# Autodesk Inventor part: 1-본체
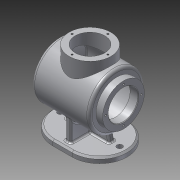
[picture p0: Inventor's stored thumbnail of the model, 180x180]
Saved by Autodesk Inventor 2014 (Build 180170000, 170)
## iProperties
Created: 2016-04
Part Number: 1-본체
Material: 알루미늄 6061
Document SubType Name: Modeling
Designer: owner
Density: 2.71 g/cm^3
Appearance: 알루미늄 - 평지
Mass: 916.245 g
Surface Area: 1253.5 cm^2
Volume: 338.098 cm^3
Author: owner
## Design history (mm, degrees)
sketch "스케치1"
  geometry: L1 (-67.5, 50)-(67.5, 50); L2 (67.5, 50)-(67.5, -50); L3 (67.5, -50)-(-67.5, -50); L4 (-67.5, -50)-(-67.5, 50); 3 further points
  constraints: 8 end point, 2 midpoint, 2 parallel, 1 horizontal, 1 horizontal alignment, 1 perpendicular, 1 vertical alignment
  dimensions: "d0" = 135 distance of L1.start L1.end; "d1" = 100 distance of L1.end L2.end
extrude "돌출1" new body sketch "스케치1" distance "d2" = 10; taper "d3" = 0 deg
fillet "모깎기1" dims "d4" = 50
node "작업 평면1"
sketch "스케치6"
  geometry: L1 (-67.5, 0)-(-67.5, 10) reference; L2 (67.5, 0)-(67.5, 10) reference; L3 (17.5, 10)-(67.5, 10) reference; L4 (-17.5, 10)-(17.5, 10) reference; L5 (-67.5, 10)-(-17.5, 10) reference; L6 (-61, 79)-(61, 79); L7 (67.5, 0)-(17.5, 0) reference; L8 (54.623, 129)-(-49, 129); L9 (-49, 129)-(-49, 117); L10 (-49, 117)-(-61, 117); L11 (-61, 117)-(-61, 106); L12 (52.287, 126)-(-46, 126); L13 (-46, 126)-(-46, 106); L14 (-46, 106)-(-61, 106); A1 r 199.192 centre (-138.192, 79) between (61, 79) and (54.623, 129); A2 r 196.192 centre (-138.192, 79) between (58, 79) and (52.287, 126); 2 further points
  constraints: 16 end point, 5 perpendicular, 4 point on circle, 3 parallel, 2 centre point, 2 point on line, 2 vertical alignment, 1 midpoint
  dimensions: "d53" = 79 distance between parallel lines of L6 L7; "d54" = 122 distance of L6.start L6.end; "d56" = 100 diameter of L8 L6; "d57" = 12 distance of L9.end L10.end; "d58" = 76 diameter of L10 L6; "d61" = 54 diameter of L14 L6; "d62" = 15 distance of L11.end L13.end; "d63" = 3 distance between parallel lines of L8 L12; "d64" = 3 radial gap between concentric circles of A2 A1 (= d63); "d65" = 199.19182 radius of A1
revolve "회전3" sketch "스케치6" stored, may be unused: angle "d66" = 90 deg
node "작업 평면2"
sketch "스케치7"
  geometry: C1 r 38 at (0, 0); 1 further point
  constraints: 1 centre point, 1 coincident
  dimensions: "d68" = 76 diameter of C1
extrude "돌출3" join sketch "스케치7" stored distance "d69" = 12; taper "d70" = 0 deg
node "작업 평면4"
sketch "스케치10"
  geometry: L1 (-50, 10)-(50, 10) reference; L2 (-40, 49)-(-40, 10); L3 (40, 49)-(40, 10); L4 (-40, 10)-(40, 10); A1 r 50 centre (0, 79) between (-40, 49) and (40, 49) reference; A2 r 50 centre (0, 79) between (-40, 49) and (40, 49); 1 further point
  constraints: 6 end point, 4 point on circle, 2 point on line, 1 centre point, 1 coincident, 1 collinear, 1 parallel, 1 perpendicular
  dimensions: "d73" = 40 distance from line of point (0, 0) L3; "d74" = 40 horizontal distance of L2.end point (0, 0) (= d73)
extrude "돌출4" join sketch "스케치10" stored distance "d75" = 10; taper "d76" = 0 deg
sketch "스케치11"
  geometry: C1 r 38 at (0, 0) reference; C2 r 27 at (0, 0) reference; C3 r 32.5 at (0, 0); 2 further points
  constraints: 1 centre point, 1 coincident, 1 horizontal alignment
  dimensions: "d77" = 65 diameter of C3; "d78" = 32.5 distance of C1.centre point (-32.5, 0)
hole "구멍2" sketch "스케치11" at (-32.5, 0) diameter "d79" = 3.242; stored, may be unused: countersink angle "d83" = 90 deg, drill point angle "d85" = 118 deg; dims "d80" = 8, "d81" = 4, "d82" = 2, "d84" = 10
node "작업 평면5"
sketch "스케치12"
  geometry: L1 (-49, 29)-(54.623, 29) reference; L2 (-67.5, 10)-(-17.5, 10) reference; L3 (-5, 49)-(-5, 10) reference; L4 (17.5, 10)-(-17.5, 10) reference; L5 (-40, 10)-(-36.65, 29); 1 further point
  constraints: 2 end point, 2 point on line
  dimensions: "d90" = 40 horizontal distance of point (0, 0) L5.start; "d91" = 100 deg angle of L5 L2
feature "리브1" sketch "스케치12" dims "d92" = 1, "d93" = 10, "d94" = 0, "d95" = 0, "d96" = 1, "d97" = 1
sketch "스케치13" dims "d98" = 65
  geometry: C1 r 38 at (0, 0) reference; 2 further points
  constraints: 2 horizontal alignment, 1 coincident, 2 other
hole "구멍3" sketch "스케치13" at (32.5, 0) diameter "d99" = 3.242; stored, may be unused: countersink angle "d103" = 90 deg, drill point angle "d105" = 118 deg; dims "d100" = 8, "d101" = 4, "d102" = 2, "d104" = 10
sketch "스케치14"
  geometry: C1 r 5 at (-54, 0); A1 r 50 centre (-17.5, 0) between (-17.5, 50) and (-17.5, -50) reference; 1 further point
  constraints: 1 centre point, 1 horizontal alignment
  dimensions: "d109" = 10 diameter of C1; "d110" = 54 distance of C1.centre point (0, 0)
extrude "돌출5" cut sketch "스케치14" stored distance "d111" = 10; taper "d112" = 0 deg
fillet "모깎기3" dims "d113" = 2, "d114" = 5
chamfer "모따기1" distance "d115" = 3; stored, may be unused: second distance "d116" = 2, angle "d117" = 45 deg
chamfer "모따기2" distance "d118" = 1; stored, may be unused: second distance "d119" = 2, angle "d120" = 45 deg
hole "구멍4" diameter "d123" = 54; stored, may be unused: countersink angle "d127" = 90 deg, drill point angle "d129" = 0 deg; dims "d121" = 10, "d122" = 10, "d124" = 8, "d125" = 4, "d126" = 2, "d128" = 46.75
fillet "모깎기4" dims "d130" = 3
fillet "모깎기5" dims "d131" = 3
fillet "모깎기6" dims "d132" = 3
node "작업 평면8"
  node "작업 평면7"
sketch "스케치15"
  geometry: L1 (-35.475, 15.196)-(31.208, 15.196); L2 (31.208, 15.196)-(31.208, -15.196); L3 (31.208, -15.196)-(-35.475, -15.196); L4 (-35.475, -15.196)-(-35.475, 15.196); L5 (50, -79)-(-50, -79) reference; C1 r 28 at (0, 0) reference; 4 further points
  constraints: 2 midpoint, 1 point on line, 1 vertical alignment, 2 other
  dimensions: "d134" = 79 distance from line of point (31.208, 0) L5; "d135" = 15.19599 distance from line of C1.centre L1; "d136" = 30.39198 distance of L1.end L2.end; "d137" = 66.68296 distance of L2.end L3.end; "d138" = 31.20783 horizontal distance of L1.end C1.centre
extrude "돌출6" join sketch "스케치15" stored distance "d139" = 10; taper "d140" = 0 deg
node "솔리드1"
pattern_circular "원형 패턴1" dims angle "d87" = 360 deg
mirror "대칭1"
pattern_circular "원형 패턴2" dims angle "d107" = 360 deg
mirror "대칭2"
node "작업 평면6"
other parameters: "d5" = 0, "d30" = 5, "d67" = -144, "d72" = 0, "d89" = 0, "d133" = 0.5
